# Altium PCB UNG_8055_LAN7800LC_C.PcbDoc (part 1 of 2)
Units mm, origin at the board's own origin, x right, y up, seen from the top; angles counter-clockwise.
Board outline 54.74 x 22.1 mm, 4 copper layers (Top Layer 1, Inner Layer 2, Internal Plane 3, Bottom Layer 4), stack 1.529 mm thick; 68 components, 53 nets, 222 pads, 271 vias.
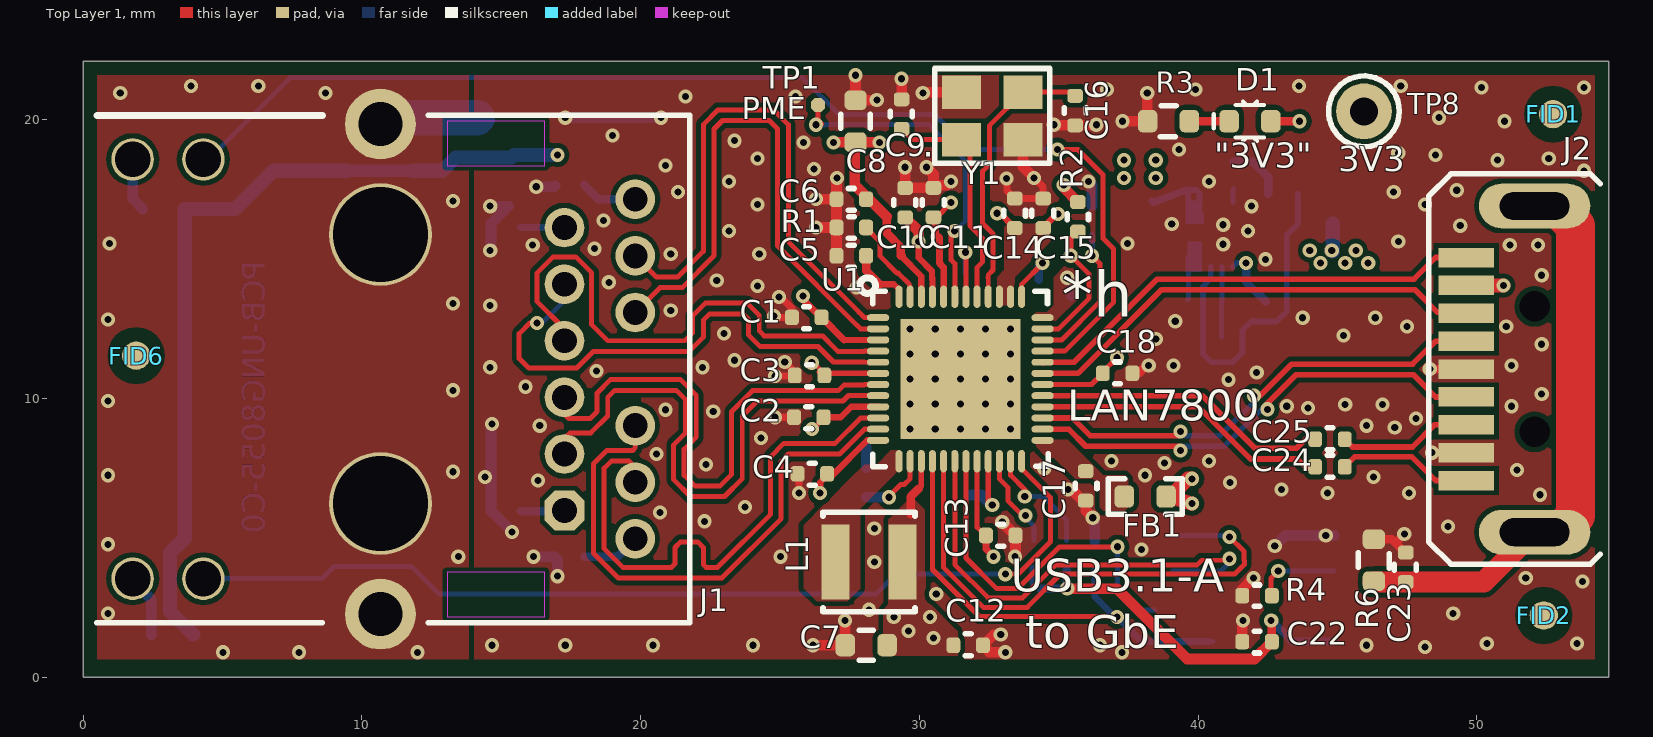
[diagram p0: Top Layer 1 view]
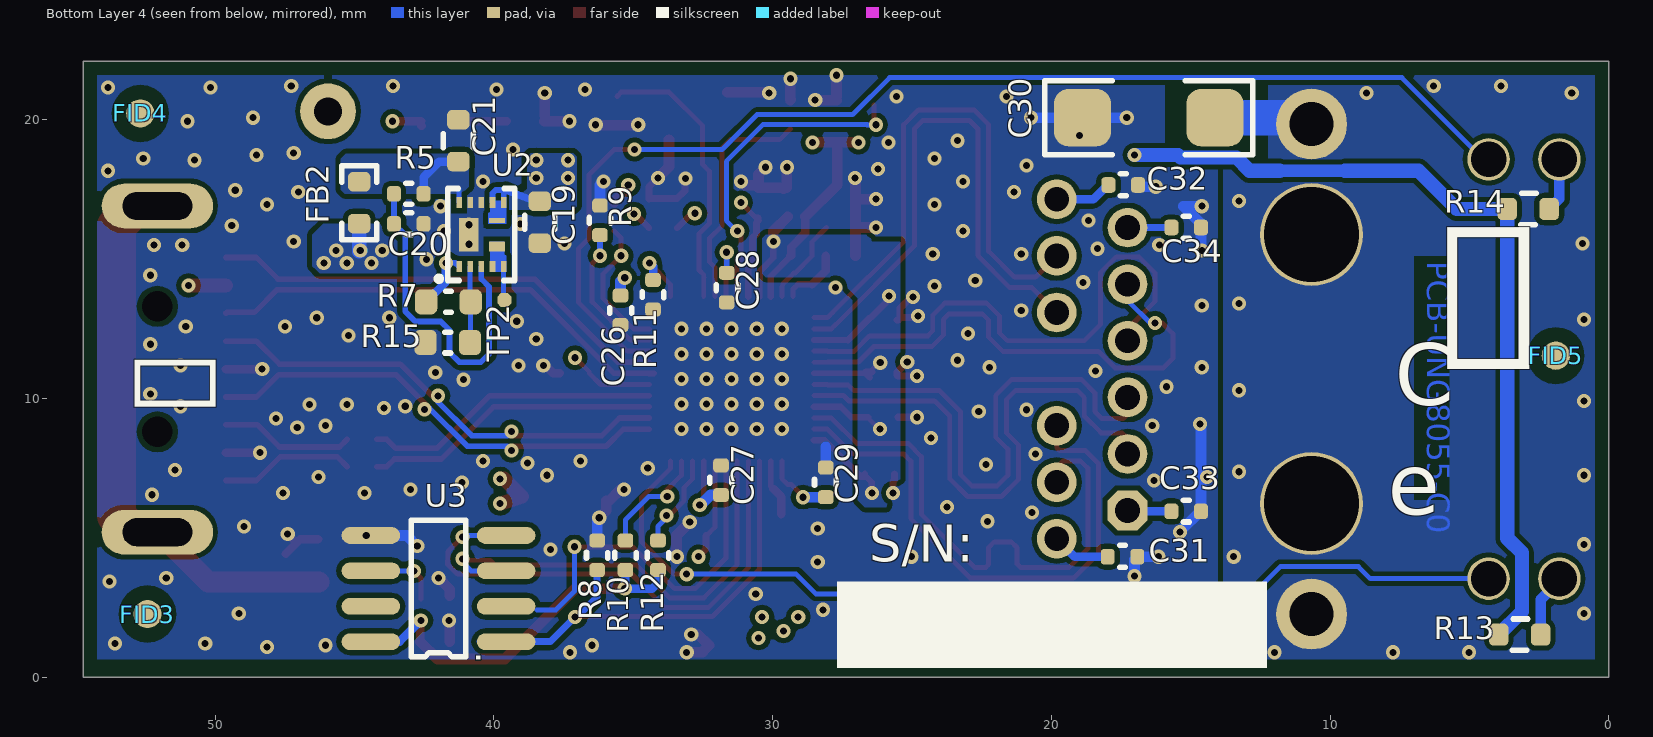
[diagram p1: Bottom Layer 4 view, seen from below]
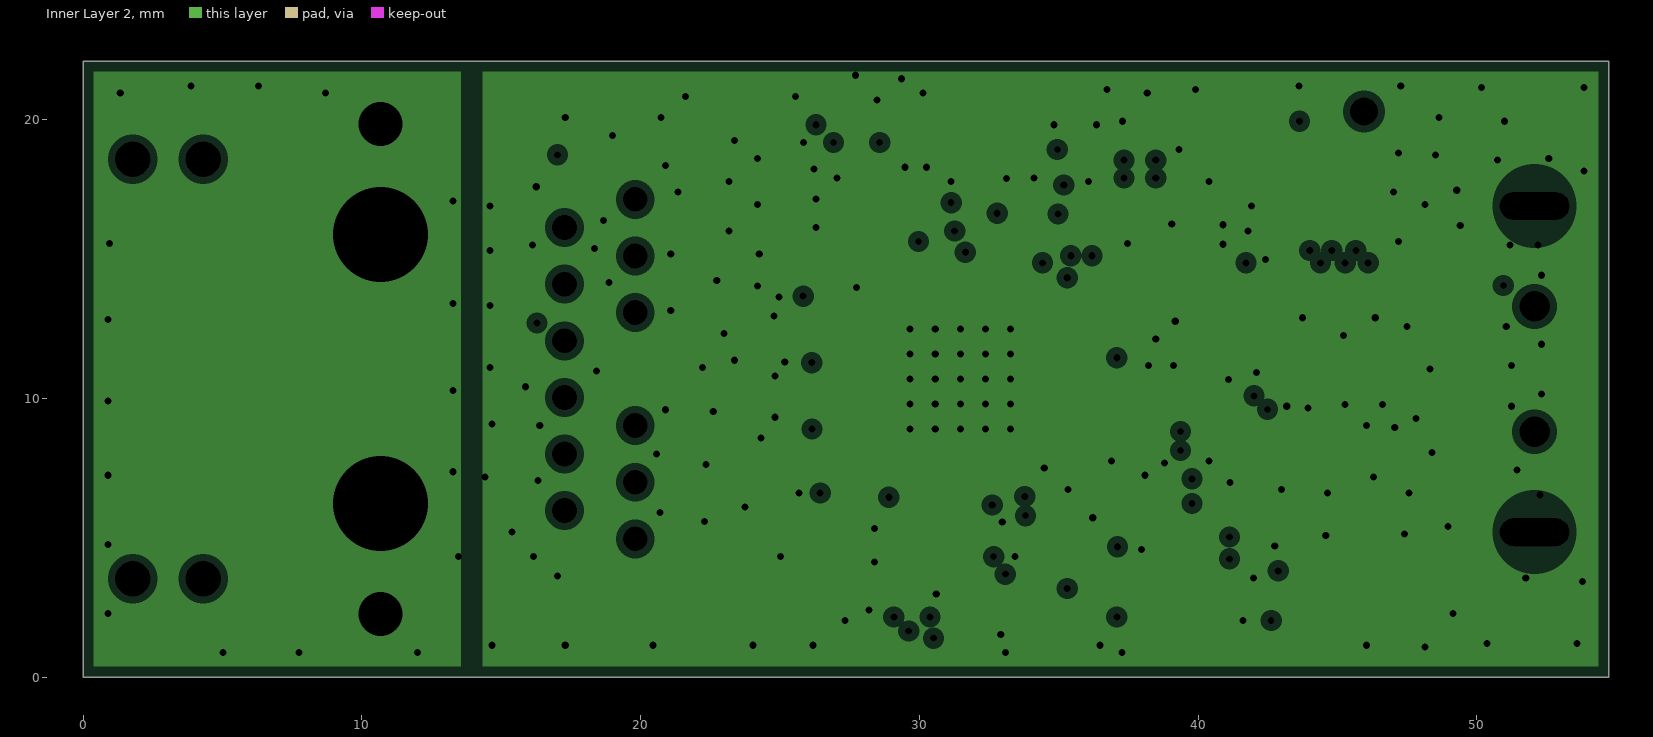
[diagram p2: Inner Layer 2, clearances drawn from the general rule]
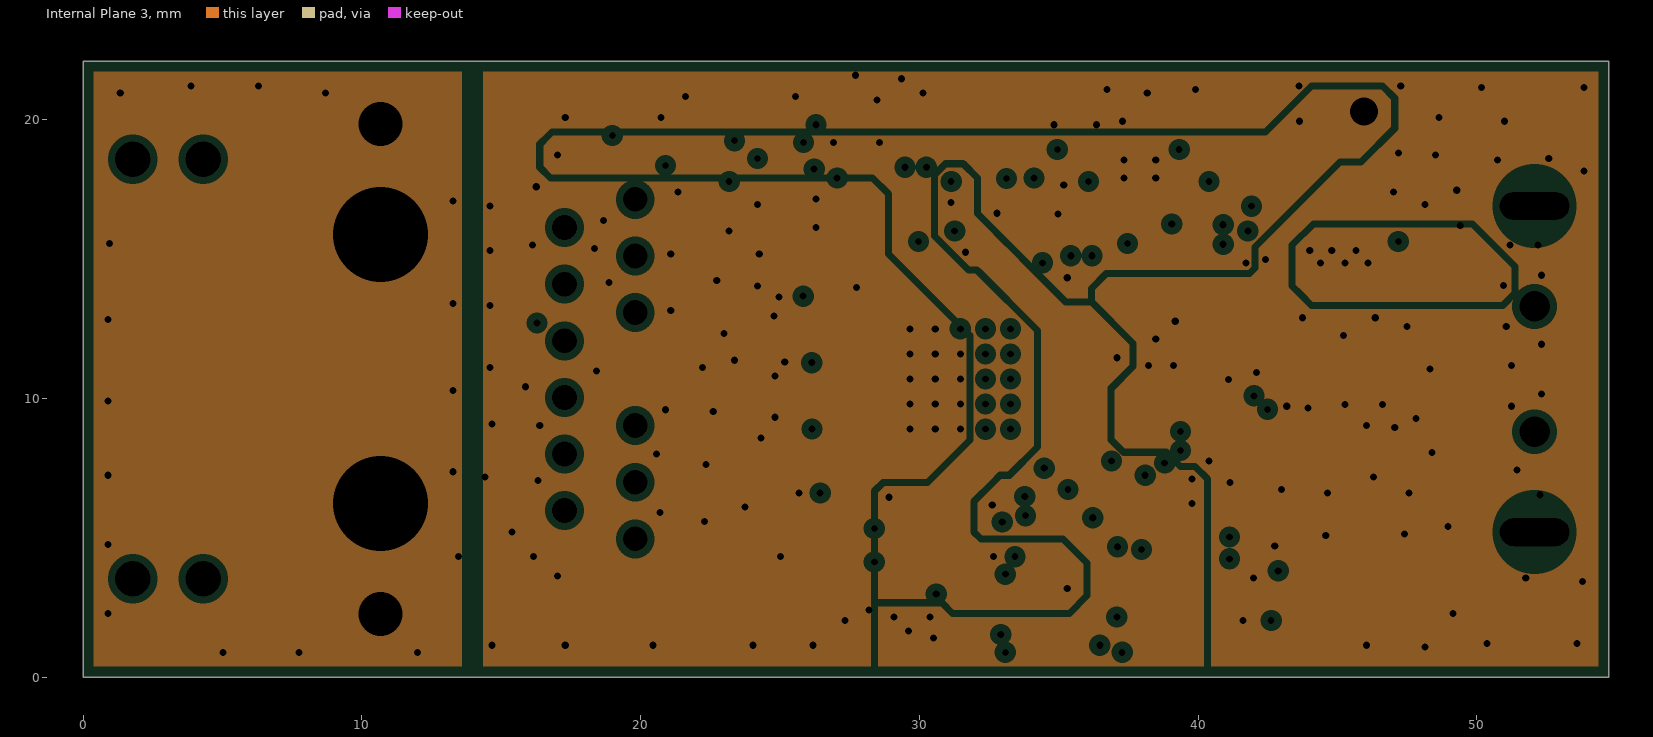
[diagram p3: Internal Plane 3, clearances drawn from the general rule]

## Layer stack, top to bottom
Top Solder: solder mask 0.0102, Solder Resist, Dk 3.5
Top Layer 1: signal copper 0.0533
Dielectric1: core 0.1092, 370HR(1ply 1080&1ply 106), Dk 4.04
Inner Layer 2: plane copper 0.0686
Dielectric 2: prepreg 1.0668, 370HR, Dk 4.04
Internal Plane 3: plane copper 0.0686
Dielectric 3: core 0.1092, 370HR(1ply 1080&1ply 106), Dk 4.04
Bottom Layer 4: signal copper 0.0533
Bottom Solder: solder mask 0.0102, Solder Resist, Dk 3.5

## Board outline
0,0 54.737,0 54.737,22.098 0,22.098

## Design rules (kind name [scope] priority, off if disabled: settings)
AssemblyTestPointUsage [All] p1 off:
AssemblyTestpoint [All] p1 off: testpointundercomponent=TRUE minsize=1.016 maxsize=2.54 preferedsize=1.524 minholesize=0 maxholesize=1.016 preferedholesize=0.813 testpointgrid=0.025 usegrid=TRUE gridtolerance=0 allowsidetop=TRUE allowsidebottom=TRUE
Clearance Dut_rules [WithinRoom('Dut_Room')] p1: gap=0.127 ignorepadtopadclearanceinfootprint=FALSE except(0: Arc-Hole Track-Hole SMDPad-Hole THPad-Hole Via-Hole Fill-Hole Poly-Hole Region-Hole Text-Hole)
Clearance USB_2_GND [InNetClass('Diff_90') vs InNet('GND')] p2: gap=0.178 ignorepadtopadclearanceinfootprint=FALSE except(0: Arc-Hole Track-Hole SMDPad-Hole THPad-Hole Via-Hole Fill-Hole Poly-Hole Region-Hole Text-Hole; 0.14: SMDPad-SMDPad; 0.152: Track-Track Track-SMDPad; 0.635: Track-Poly)
Clearance [All] p3: gap=0.178 ignorepadtopadclearanceinfootprint=FALSE except(0: Arc-Hole Track-Hole SMDPad-Hole THPad-Hole Via-Hole Fill-Hole Poly-Hole Region-Hole Text-Hole; 0.14: SMDPad-SMDPad; 0.152: Track-Track Track-SMDPad)
ComponentClearance [All] p1: gap=0 collisioncheckmode=3 verticalgap=0 showdistances=FALSE
DiffPairsRouting DiffPairsRouting_GBE [InNetClass('GBE')] p1: maxlimit=0.206 minlimit=0.201 mostfreqgap=0.203 toplayer_minwidth=0.175 toplayer_maxwidth=0.206 toplayer_prefwidth=0.178 bottomlayer_minwidth=0.175 bottomlayer_maxwidth=0.206 bottomlayer_prefwidth=0.178 maxuncoupledlength=12.7
DiffPairsRouting DiffPairsRouting_2P0 [InNetClass('Diff_90')] p2: maxlimit=0.203 minlimit=0.178 mostfreqgap=0.178 toplayer_minwidth=0.127 toplayer_maxwidth=0.208 toplayer_prefwidth=0.203 bottomlayer_minwidth=0.127 bottomlayer_maxwidth=0.208 bottomlayer_prefwidth=0.203 maxuncoupledlength=12.7
FabricationTestPointUsage TestPointUsage [All] p1 off: valid=0 allowmultiple=FALSE
FabricationTestpoint Testpoint [All] p1 off: side=3 testpointundercomponent=TRUE minsize=1.016 maxsize=2.54 preferedsize=1.524 minholesize=0 maxholesize=1.016 preferedholesize=0.813 testpointgrid=0.025 allowsidetop=TRUE allowsidebottom=TRUE usegrid=TRUE gridtolerance=0
HoleSize [All] p1: absolutevalues=TRUE maxlimit=5 minlimit=0.254 maxpercent=80.000 minpercent=20.000
MatchedLengths MatchedLengths2P0 [InNetClass('USB2.')] p1: tolerance=1.27 checknetsindiffpair=TRUE checkdiffpairvsdiffpair=FALSE checkxsignals=FALSE checkothers=FALSE
MatchedLengths MatchedLengths_GBE [InNetClass('GBE')] p2: tolerance=1.27 checknetsindiffpair=FALSE checkdiffpairvsdiffpair=TRUE checkxsignals=TRUE checkothers=TRUE
MatchedLengths MatchedLengths3P0 [InNetClass('USB3.')] p3: tolerance=0.127 checknetsindiffpair=TRUE checkdiffpairvsdiffpair=FALSE checkxsignals=FALSE checkothers=FALSE
MinimumSolderMaskSliver [All] p1: minsoldermaskwidth=0
NetsToIgnore [InNet('EARTH')] p1:
PlaneClearance [All] p1: clearance=0.254
PlaneConnect PlaneConnect_via [isVia] p1: planeconnectstyle=Direct reliefexpansion=0.5 reliefentries=4 reliefconductorwidth=0.3 reliefairgap=0.3
PlaneConnect [All] p2: planeconnectstyle=Relief reliefexpansion=0.381 reliefentries=4 reliefconductorwidth=0.457 reliefairgap=0.254
PolygonConnect PolygonConnect_top [All vs IsNamedPolygon('Top Layer-No Net')] p1: connectstyle=Direct reliefconductorwidth=0.254 reliefentries=4 polygonreliefangle="90 Angle" airgapwidth=0.254
PolygonConnect PolygonConnect_VIA [All vs iSVia] p2: connectstyle=Direct reliefconductorwidth=0.254 reliefentries=4 polygonreliefangle="90 Angle" airgapwidth=0.254
RoomDefinition UNG8055_EVB_LAN7800LC [InComponentClass('UNG8055_EVB_LAN7800LC')] p1: confinementstyle=ConfineIn formatcopy=TRUE lockcomponents=FALSE outline -88.255,-147.49 -37.455,-147.49 -37.455,-122.09 -88.255,-122.09
RoutingVias [All] p1: holewidth=0.254 width=0.508 viastyle="Through Hole" minholewidth=0.254 minwidth=0.495 maxholewidth=0.381 maxwidth=0.66
SilkToBoardRegionClearance SilkToBoardRegionClearance_1 [All] p1 off:
SilkToSilkClearance [All] p1: silktosilkclearance=0.127
SilkToSolderMaskClearance SilkscreenOverComponentPads [IsPad] p1: minsilkscreentomaskgap=0.127 clearancetoexposedcopper=TRUE
SolderMaskExpansion [All] p1: expansion=0.064
Width [All] p1: maxlimit=3.048 minlimit=0.152 preferedwidth=0.178 minimp=50.000000 maximp=50.000000 favimp=50.000000
17 further rules are at their usual default settings.

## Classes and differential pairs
net class GBE: TR0_N TR0_P TR1_N TR1_P TR2_N TR2_P TR3_N TR3_P
net class Power: 3V3_BOARD 5V_BOARD GND RJ45_CHASSIS VBUS VDD12 VDD12_SW_OUT VDD25
net class USB2.: USB2D_N USB2D_P
net class USB3.: USB3RX_N USB3RX_P USB3TX1_N USB3TX1_P USB3TX_N USB3TX_P
differential pair USB3TX1: +USB3TX1_P -USB3TX1_N
differential pair TR3: +TR3_P -TR3_N
differential pair TR2: +TR2_P -TR2_N
differential pair TR1: +TR1_P -TR1_N
differential pair TR0: +TR0_P -TR0_N
differential pair USB3RX: +USB3RX_P -USB3RX_N
differential pair USB2D: +USB2D_P -USB2D_N
differential pair USB3TX: +USB3TX_P -USB3TX_N

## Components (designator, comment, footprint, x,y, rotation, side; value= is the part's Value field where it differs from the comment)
C1 "Capacitor NP" CAP_C_0402 25.959,12.903 r0 top value=0.1uF
C2 "Capacitor NP" CAP_C_0402 26.035,9.322 r0 top value=0.1uF
C3 "Capacitor NP" CAP_C_0402 26.06,10.82 r0 top value=0.1uF
C4 "Capacitor NP" CAP_C_0402 26.162,7.29 r0 top value=0.1uF
C5 "Capacitor NP" CAP_C_0402 27.559,15.113 r0 top value=1uF
C6 "Capacitor NP" CAP_C_0402 27.559,17.145 r0 top value=1uF
C7 "Capacitor NP" CAP_C_0603 28.092,1.143 r0 top value=22uF
C8 "Capacitor NP" CAP_C_0603 27.711,19.939 r270 top value=10uF
C9 "Capacitor NP" CAP_C_0402 29.362,20.193 r270 top value=16pF
C10 "Capacitor NP" CAP_C_0402 29.489,17.018 r270 top value=1uF
C11 "Capacitor NP" CAP_C_0402 30.505,17.018 r270 top value=0.1uF
C12 "Capacitor NP" CAP_C_0402 31.75,1.143 r180 top value=0.1uF
C13 "Capacitor NP" CAP_C_0402 32.918,5.08 r180 top value=0.1uF
C14 "Capacitor NP" CAP_C_0402 33.426,16.637 r270 top value=0.1uF
C15 "Capacitor NP" CAP_C_0402 34.442,16.637 r270 top value=0.1uF
C16 "Capacitor NP" CAP_C_0402 35.585,20.32 r90 top value=16pF
C17 "Capacitor NP" CAP_C_0402 35.966,6.858 r90 top value=1uF
C18 "Capacitor NP" CAP_C_0402 37.109,10.897 r180 top value=0.1uF
C19 "Capacitor NP" CAP_C_0603 38.354,16.319 r90 bottom value=10uF
C20 "Capacitor NP" CAP_C_0402 43.053,16.256 r0 bottom value=0.1uF
C21 "Capacitor NP" CAP_C_0603 41.275,19.241 r270 bottom value=10uF
C22 "Capacitor NP" CAP_C_0402 42.113,1.27 r0 top value=0.1uF
C23 "Capacitor NP" CAP_C_0402 47.447,3.937 r270 top value=0.1uF
C24 "Capacitor NP" CAP_C_0402 44.729,7.544 r180 top value=0.1uF
C25 "Capacitor NP" CAP_C_0402 44.729,8.531 r180 top value=0.1uF
C26 "Capacitor NP" CAP_C_0402 35.458,13.157 r90 bottom value=0.1uF
C27 "Capacitor NP" CAP_C_0402 31.852,7.061 r270 bottom value=0.1uF
C28 "Capacitor NP" CAP_C_0402 31.648,13.97 r90 bottom value=0.1uF
C29 "Capacitor NP" CAP_C_0402 28.092,6.985 r270 bottom value=0.1uF
C30 "Capacitor NP" Cap_C_1808 16.51,20.066 r180 bottom value=1000pF
C31 "Capacitor NP" CAP_C_0402 17.45,4.318 r0 bottom value=0.1uF
C32 "Capacitor NP" CAP_C_0402 17.424,17.653 r0 bottom value=0.1uF
C33 "Capacitor NP" CAP_C_0402 15.164,5.944 r0 bottom value=0.1uF
C34 "Capacitor NP" CAP_C_0402 15.164,16.129 r0 bottom value=0.1uF
D1 "LED_green" LED_0603_GREEN 41.859,19.939 r180 top value=GREEN
FB1 "Ferrite Bead" IND_C_0603 38.1,6.477 r0 top value=120R
FB2 "Ferrite Bead" Ind_C_0603 44.831,17.018 r90 bottom value=120R
FID1 "FIDUCIAL" FIDUCIAL 52.73,20.193 r90 top
FID2 "FIDUCIAL" FIDUCIAL 52.4,2.21 r90 top
FID3 "FIDUCIAL" FIDUCIAL 52.426,2.261 r90 bottom
FID4 "FIDUCIAL" FIDUCIAL 52.68,20.218 r90 bottom
FID5 "FIDUCIAL" FIDUCIAL 1.905,11.532 r90 bottom
FID6 "FIDUCIAL" FIDUCIAL 1.905,11.532 r90 top
J1 "CON RJ-45 RJMG2012211A0FR" CON_JACK_RJ45_1PORT_LED_RJMG2012211A0FR 10.668,11.049 r270 top value="MODULAR RJ45"
J2 "CON USB3.0 A-B" CON_USB3.0-A_PLUG_SMD_RA_WE_692112030100 52.07,11.049 r90 top locked value="USB3.0 STD-A MALE"
L1 "Inductor" IND_WE_74404032033_L3W3H1.5 28.194,4.127 r0 top value=3.3uH
R1 "Resistor" RES_C_0402 27.559,16.129 r180 top value=2k
R2 "Resistor" RES_C_0402 35.687,16.51 r90 top value=10k
R3 "Resistor" RES_C_0603#1 38.938,19.939 r0 top value=1k
R4 "Resistor" RES_C_0402 42.113,2.921 r0 top value=10k
R5 "Resistor" RES_C_0402 43.053,17.335 r180 bottom value=10k
R6 "Resistor" RES_C_0603#1 46.304,4.191 r90 top value=330R
R7 "Resistor" RES_C_0603#2 41.63,13.462 r0 bottom value=866k
R8 "Resistor" RES_C_0402 36.297,4.369 r270 bottom value=10k
R9 "Resistor" RES_C_0402 36.195,16.383 r270 bottom value=10k
R10 "Resistor" RES_C_0402 35.281,4.369 r270 bottom value=10k
R11 "Resistor" RES_C_0402 34.29,13.716 r90 bottom value=12k
R12 "Resistor" RES_C_0402 34.112,4.369 r270 bottom value=10k
R13 "Resistor" RES_C_0603#1 3.2,1.524 r0 bottom value=1k
R14 "Resistor" RES_C_0603#1 2.896,16.789 r0 bottom value=1k
R15 "Resistor" RES_C_0603#2 41.656,12.002 r180 bottom value=200k
TP1 "Jumper" TP_PAD_SMT_20OCTAGONAL 26.365,20.523 r90 top
TP2 "Jumper" TP_PAD_SMT_20OCTAGONAL 39.624,13.525 r90 bottom
TP8 "Test Point" CON_TP_TH_V_ORN_KEC_5003 45.949,20.295 r90 top value=Orange
U1 "LAN7800 QFN-48 TEST" QFN-48_6X6 31.471,10.693 r0 top value=LAN7800/VSX
U2 "MIC33030-AYHJ MLF-10" MLF-10_2.5x2.0mm 40.449,15.875 r90 bottom value=MIC33030-AYHJ
U3 "93XX66A_B_C PDIP-8_SOIC-8_TSSOP-8_MSOP-8" SOIC-8_150MIL 41.986,3.175 r0 bottom value=93AA66C
Y1 "Crystal 4 Pins" CRYSTAL_ABM8G 32.614,20.13 r0 top value=25Mhz

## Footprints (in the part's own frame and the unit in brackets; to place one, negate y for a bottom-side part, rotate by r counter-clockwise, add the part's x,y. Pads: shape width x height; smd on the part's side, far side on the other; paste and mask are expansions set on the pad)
CAP_C_0402 [mm] "Chip Capacitor 2-Leads, Body 1.6x0.8mm, IPC Medium Density"
  rrect50% 0.5x0.56 smd: 1(-0.53,0) 2(0.53,0)
  silkscreen extent -0.1,-0.41 0.1,0.38, body extent -0.5,-0.25 0.5,0.25, height 0.49
CAP_C_0603 [mm] "Chip Capacitor 2-Leads, Body 1.6x0.8mm, IPC Medium Density"
  rrect50% 0.7x0.8 smd: 1(-0.75,0) 2(0.75,0)
  silkscreen extent -0.25,-0.53 0.25,0.53, body extent -0.8,-0.4 0.8,0.4, height 0.79
Cap_C_1808 [mm] "Chip Capacitor 2-Leads, Body 4.5 x 2.0mm, IPC Medium Density"
  rrect50% 2.05x2.05 smd: 1(-2.375,0) 2(2.375,0)
  silkscreen extent -3.72,-1.33 3.72,1.33, body extent -2.25,-1.03 2.25,1, height 1.25
CON_JACK_RJ45_1PORT_LED_RJMG2012211A0FR [mm] "CONN MAGJACK 1PORT 1000 BASE-T AMPHENOL RJMG2012211A0FR"
  round 2.54 hole 1.57: 0(-8.79,0) 0(8.79,0)
  round 3.683 hole 3.4: 0(-4.825,0) 0(4.825,0)
  oct 1.422x1.422 hole 0.89: 1(5.075,6.6)
  round 1.422 hole 0.89: 2(3.045,6.6) 3(1.015,6.6) 4(-1.015,6.6) 5(-3.045,6.6) 6(-5.075,6.6) 7(6.09,9.14) 8(4.06,9.14) 9(2.03,9.14) 10(-2.03,9.14) 11(-4.06,9.14) 12(-6.09,9.14)
  round 1.524 hole 1.27: 13(7.52,-6.35) 14(7.52,-8.89) 15(-7.52,-6.35) 16(-7.52,-8.89)
  Top Layer 1 keep-out region: -8.89,2.39 -7.29,2.39 -7.29,5.89 -8.89,5.89
  Top Layer 1 keep-out region: 7.29,2.39 8.89,2.39 8.89,5.89 7.29,5.89
  silkscreen extent -9.1,-10.18 9.1,11.1, body extent -9.96,-13.27 9.96,10.87, height 11.96
CON_TP_TH_V_ORN_KEC_5003 [mm] "TEST POINT PC MULTI PURPOSE MINI ORN"
  round 2 hole 1: 1(0,0)
  silkscreen extent -1.27,-1.27 1.27,1.27, body extent -1.27,-1.27 1.27,1.27, height 4.89
CON_USB3.0-A_PLUG_SMD_RA_WE_692112030100 [mm] "CONN USB 3.0 A PLUG SMD R/A EDGE L=18.8mm, W=12mm, H=4.5mm"
  oval 1.6x4 hole 1 slot 2.5 at 90 deg: 0(-5.85,0) 0(5.85,0)
  rect 0.7x2 smd: 1(3,2.45) 2(1,2.45) 3(-1,2.45) 4(-3,2.45) 5(-4,2.45) 6(-2,2.45) 7(0,2.45) 8(2,2.45) 9(4,2.45)
  round 0 hole 1.1 unplated paste-1 mask+0.65: MH(-2.25,0) MH(2.25,0)
  silkscreen extent -7,-2.35 7,3.8, body extent -6,-17.8 6,2.95, height 1.86
CRYSTAL_ABM8G [mil]
  rect 55x47 smd: 1(-43.5,-33.5) 2(43.5,-33.5) 3(43.5,33.5) 4(-43.5,33.5)
  silkscreen extent -81,-67 81,67, body extent -63,-49 63,49, height 40
FIDUCIAL [mil]
  round 40 smd mask+20: 1(0,0)
  Top Layer 1 pour cut-out: 40.35,0 38.97,10.44 34.94,20.17 28.53,28.53 20.17,34.94 10.44,38.97 0,40.35 0,40.35 -10.44,38.97 -20.17,34.94 -28.53,28.53 -34.94,20.17 -38.97,10.44 -40.35,0 -40.35,0 -38.97,-10.44 -34.94,-20.17 -28.53,-28.53 -20.17,-34.94 -10.44,-38.97 0,-40.35 0,-40.35 10.44,-38.97 20.17,-34.94 28.53,-28.53 34.94,-20.17 38.97,-10.44 40.35,0
  body extent -40,-40 40,40, height 0
IND_C_0603 [mm] "Chip Inductor 2-Leads, Body 1.6x0.8mm, IPC Medium Density"
  rrect50% 0.7x0.8 smd: 1(-0.75,0) 2(0.75,0)
  silkscreen extent -1.33,-0.63 1.33,0.63, body extent -1.33,-0.63 1.32,0.63, height 0.81
Ind_C_0603 [mm] "Chip Inductor 2-Leads, Body 1.6x0.8mm, IPC Medium Density"
  rrect50% 0.7x0.8 smd: 1(-0.75,0) 2(0.75,0)
  silkscreen extent -1.33,-0.63 1.33,0.63, body extent -1.33,-0.63 1.32,0.63, height 0.81
IND_WE_74404032033_L3W3H1.5 [mm]
  rect 1x2.7 smd: 1(-1.2,0) 2(1.2,0)
  silkscreen extent -1.65,-1.78 1.65,1.78, body extent -1.48,-1.5 1.52,1.5, height 1.5
LED_0603_GREEN [mm] "LED chip 0603 - GREEN"
  rrect50% 0.7x0.8 smd: 1(-0.75,0) 2(0.75,0)
  silkscreen extent -0.51,-0.71 1.3,0.71, body extent -1.33,-0.63 1.32,0.63, height 0.6
MLF-10_2.5x2.0mm [mm] "MLF 10-Leads, Body 2.55x2.05mm (max), Pitch 0.40mm, IPC Medium Density"
  rrect0% 0.4x0.2 smd mask+0.05: 1(-1.15,0.8) 2(-1.15,0.4) 3(-1.15,0) 4(-1.15,-0.4) 5(-1.15,-0.8) 6(1.15,-0.8) 7(1.15,-0.4) 8(1.15,0) 9(1.15,0.4) 10(1.15,0.8)
  rect 0.36x0.58 smd mask+0.05: 4(-0.43,-0.56)
  rect 0.18x0.58 smd mask+0.05: 7(0.51,-0.56)
  rect 1.2x0.7 smd mask+0.05: EP(0,0.45)
  silkscreen extent -1.65,-1.2 1.65,1.52, body extent -1.28,-1.02 1.28,1.03, height 1.15
QFN-48_6X6 [mm] "QFN, 48-Leads, Body 6x6mm, Pitch 0.4mm, Thermal Pad 4.3mmsq"
  oval 0.8x0.25 smd: 1(-2.95,2.2) 2(-2.95,1.8) 3(-2.95,1.4) 4(-2.95,1) 5(-2.95,0.6) 6(-2.95,0.2) 7(-2.95,-0.2) 8(-2.95,-0.6) 9(-2.95,-1) 10(-2.95,-1.4) 11(-2.95,-1.8) 12(-2.95,-2.2) 25(2.95,-2.2) 26(2.95,-1.8) 27(2.95,-1.4) 28(2.95,-1) 29(2.95,-0.6) 30(2.95,-0.2) 31(2.95,0.2) 32(2.95,0.6) 33(2.95,1) 34(2.95,1.4) 35(2.95,1.8) 36(2.95,2.2)
  oval 0.25x0.8 smd: 13(-2.2,-2.95) 14(-1.8,-2.95) 15(-1.4,-2.95) 16(-1,-2.95) 17(-0.6,-2.95) 18(-0.2,-2.95) 19(0.2,-2.95) 20(0.6,-2.95) 21(1,-2.95) 22(1.4,-2.95) 23(1.8,-2.95) 24(2.2,-2.95) 37(2.2,2.95) 38(1.8,2.95) 39(1.4,2.95) 40(1,2.95) 41(0.6,2.95) 42(0.2,2.95) 43(-0.2,2.95) 44(-0.6,2.95) 45(-1,2.95) 46(-1.4,2.95) 47(-1.8,2.95) 48(-2.2,2.95)
  rect 4.3x4.3 / inner round 0.508 / far side round 0.508 hole 0.254 mask+0.051: 49(0,0)
  silkscreen extent -3.6,-3.15 3.15,3.63, body extent -3.02,-3.02 3.02,3.02, height 0.91
RES_C_0402 [mm] "Chip Resistor, 2-Leads, Body 1.0x0.5mm, IPC Medium Density"
  rrect50% 0.5x0.56 smd: 1(-0.53,0) 2(0.53,0)
  silkscreen extent -0.1,-0.38 0.1,0.38, body extent -0.5,-0.25 0.5,0.25, height 0.34
RES_C_0603#1 [mm] "Chip Resistor, 2-Leads, Body 1.6x0.8mm, IPC Medium Density"
  rrect50% 0.7x0.8 smd: 1(-0.75,0) 2(0.75,0)
  silkscreen extent -0.29,-0.56 0.27,0.56, body extent -0.8,-0.4 0.8,0.4, height 0.45
RES_C_0603#2 [mm] "Chip Resistor, 2-Leads, Body 1.6x0.8mm, IPC Medium Density"
  rrect50% 0.8x0.9 smd: 1(-0.8,0) 2(0.8,0)
  silkscreen extent -0.1,-0.38 0.1,0.38, body extent -0.8,-0.4 0.8,0.4, height 0.3
SOIC-8_150MIL [mm] "SOIC-8 Narrow"
  oval 2.1x0.6 smd: 1(-2.425,1.905) 2(-2.425,0.635) 3(-2.425,-0.635) 4(-2.425,-1.905) 5(2.425,-1.905) 6(2.425,-0.635) 7(2.425,0.635) 8(2.425,1.905)
  silkscreen extent -0.97,-2.45 0.98,2.45, body extent -2.96,-2.5 3.06,2.5, height 1.75
TP_PAD_SMT_20OCTAGONAL [mil] "TEST POINT, SMT PAD20OCTAGONAL"
  oct 20x20 smd: 1(0,0)

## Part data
C1 C2 C3 C4 C11 C12 C13 C14 C15 C18 C20 C22 C23 C24 C25 C26 C27 C28 C29 C31 C32 C33 C34: library part CAP1337, "Capacitor", Manufacturer 1="TDK Corporation", Manufacturer Part Number 1=CGA2B3X7R1V104K050BB, Operating Temperature="-55C to 125C", Package=0402, Supplier Part Number 1=445-6901-1-ND, Temperature Coeffcient=X7R, Tolerance=10%, Voltage=35V
C5 C6 C10 C17: library part CAP1065, "Capacitor", Manufacturer 1="TDK Corporation", Manufacturer Part Number 1=C1005X5R1C105K, Operating Temperature="-55C to +85C", Package=0402, Supplier Part Number 1=445-4978-2-ND, Temperature Coeffcient=X5R, Tolerance=10%, Voltage=16V
C7: library part CAP1366, "Capacitor", Manufacturer 1="Samsung Electro-Mechanics America, Inc", Manufacturer Part Number 1=CL10A226MQ8NRNC, Operating Temperature="-55C to +85C", Package=0603, Supplier Part Number 1=1276-1193-1-ND, Temperature Coeffcient=X5R, Voltage=6.3V
C8 C19 C21: library part CAP1461, "Capacitor", Manufacturer 1="Murata Electronics North America", Manufacturer Part Number 1=GRM188R61E106MA73D, Operating Temperature="-55C to 85C", Package=0603, Supplier Part Number 1=490-7202-1-ND, Temperature Coeffcient=X5R, Tolerance=±20%, Voltage=25V
C9 C16: library part CAP1767, "Capacitor", Manufacturer 1="Murata Electronics North America", Manufacturer Part Number 1=GRM1555C1H160JA01D, Operating Temperature="-55°C ~ 125°C", Package=0402, Supplier Part Number 1=490-5926-1-ND, Temperature Coeffcient=NPO, Tolerance=5%, Voltage=50V
C30: library part CAP1775, "Capacitor", Manufacturer 1="Murata Electronics North America", Manufacturer Part Number 1=GR442QR73D102KW01L, Operating Temperature="-55°C ~ 125°C", Supplier Part Number 1=490-8145-1-ND, Temperature Coeffcient=X7R, Tolerance=10%, Voltage=2KV
D1: library part DIODE1155, "LED", Forward Current=30mA, Manufacturer 1="Lite-On Inc", Manufacturer 2=Ledtech, Manufacturer Part Number 1=LTST-C191KGKT, Manufacturer Part Number 2=LT8A23-54-SB96-T5, Operating Temperature="-55C to +85C", Power=75mW, Reverse Voltage=5V, Supplier Part Number 1=160-1446-1-ND
FB1 FB2: library part FB1003, Manufacturer 1="TDK Corporation", Manufacturer Part Number 1=MMZ1608B121CTAH0, Supplier Part Number 1=445-2164-1-ND
J1: library part CON1827, Manufacturer 1="Amphenol Commercial Products", Manufacturer Part Number 1=RJMG2012211A0FR, Supplier Part Number 1=RJMG2012211A0FR-ND
J2: library part CON1255, "Connector USB", Current=1.8A, Manufacturer 1="Wurth Electronics Inc", Manufacturer Part Number 1=692112030100, Supplier Part Number 1=732-3157-ND, Voltage=30V
L1: library part IND1557, Manufacturer 1="Wurth Electronics Inc.", Manufacturer Part Number 1=74404032033, Operating Temperature="-40°C ~ 125°C", Package=3015, Saturation Current=1.5A, Supplier Part Number 1=732-5494-1-ND, Test Frequency=100kHz
R1: library part RES1437, Manufacturer 1="Panasonic Electronic Components", Manufacturer Part Number 1=ERJ-2RKF2001X, Operating Temperature="-55°C ~ 155°C", Package=0402, Power=1/10W, Supplier Part Number 1=P2.00KLCT-ND, Temperature Coeffcient=±100ppm/°C, Tolerance=1%
R2 R4 R5 R8 R9 R10 R12: library part RSMT1019, Manufacturer 1=Panasonic, Manufacturer Part Number 1=ERJ-2RKF1002X, Operating Temperature="-55C to +155C", Package=0402, Power=1/10W, Supplier Part Number 1=P10.0KLCT-ND, Temperature Coeffcient=100ppm/C, Tolerance=1%, Voltage=50V
R3 R13 R14: library part RSMT0047, Manufacturer 1=Panasonic, Manufacturer 2="KOA Speer", Manufacturer 4=ROHM, Manufacturer 6="Stackpole Electronics Inc", Manufacturer 7=Yageo, Manufacturer Part Number 1=ERJ-3GEYJ102V, Manufacturer Part Number 2=RK73B1JTTD102J, Manufacturer Part Number 3=ERJ-3GSYJ102V, Manufacturer Part Number 4=MCR03EZHJ1K, Manufacturer Part Number 5=MCR03FZHJ1001, Manufacturer Part Number 6="RMCF 1/16 1K 5% R", Manufacturer Part Number 7=RC0603JR-071KL, Operating Temperature="-55C to +155C", Package=0603, Power=1/10W, Supplier Part Number 1=P1.0KGCT-ND, Temperature Coeffcient=200ppm/C, Tolerance=5%, Voltage=75V
R6: library part RES1346, Manufacturer 1="Panasonic Electronic Components", Manufacturer Part Number 1=ERA-V33J331V, Operating Temperature="-40C to +125C", Package=0603, Power=1/16W, Supplier Part Number 1=P330CHTR-ND, Temperature Coeffcient=3300ppm/C, Tolerance=5%
R7: library part RSMT1204, Manufacturer 1=Yageo, Manufacturer Part Number 1=RC0603FR-07866KL, Operating Temperature="-55C to +155C", Package=0603, Power=1/10W, Supplier Part Number 1=311-866KHRCT-ND, Temperature Coeffcient=100ppm/C, Tolerance=1%, Voltage=75V
R11: library part RES1021, Manufacturer 1="Rohm Semiconductor", Manufacturer Part Number 1=MCR01MZPF1202, Operating Temperature="-55C to +155C", Package=0402, Power=1/16W, Supplier Part Number 1=RHM12.0KLCT-ND, Temperature Coeffcient=400ppm/C, Tolerance=1%, Voltage=50V
R15: library part RES1140, Manufacturer 1=Vishay, Manufacturer Part Number 1=CRCW0603200KFKEA, Operating Temperature="-55C to +155C", Package=0603, Power=1/10W, Supplier Part Number 1=541-200KHCT-ND, Temperature Coeffcient=100ppm/C, Tolerance=1%, Voltage=75V
TP1 TP2: library part "TEST PAD SMT 20 OCTAGON", "TEST PAD SMT 20 OCTAGON", Manufacturer=none
TP8: library part CON1282, Manufacturer 1="Keystone Electronics", Manufacturer Part Number 1=5003, Supplier Part Number 1=5003K-ND
U1: library part MIC7903, Manufacturer 1="Microchip Technology Inc", Manufacturer Part Number 1=LAN7800/VSX
U2: library part MIC7400, Manufacturer 1=Microchip, Manufacturer Part Number 1=MIC33030-AYHJ-TR, Supplier Part Number 1=576-3720-1-ND
U3: library part MIC7670, Manufacturer 1="Microchip Technology", Manufacturer Part Number 1=93AA66C-I/SN, MaxClockFreq="3 MHz", OpVoltMax=5.5, OpVoltMin=1.8, PackageType=SOIC, PackageWidth=3.90mm(.150in), Supplier Part Number 1=93AA66C-I/SN-ND, TempRange="-40C to +85C"
Y1: library part OSC1196, Load Capacitance=10pF, Manufacturer 1="Abracon LLC", Manufacturer Part Number 1=ABM8G-25.000MHZ-B4Y-T, Operating Temperature="-20°C ~ 70°C", Package=ABM8G, Supplier Part Number 1=535-10297-1-ND, Tolerance=±30ppm

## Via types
v1: diameter 0.508, hole 0.254, Top Layer 1 to Bottom Layer 4, tented both sides, 245 vias
v2: diameter 0.508, hole 0.254, Top Layer 1 to Bottom Layer 4, 26 vias

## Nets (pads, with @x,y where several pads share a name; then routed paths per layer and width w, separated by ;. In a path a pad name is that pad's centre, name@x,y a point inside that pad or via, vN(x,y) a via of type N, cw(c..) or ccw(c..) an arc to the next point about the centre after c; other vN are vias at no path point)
3V3_BOARD: C6.2 C8.2 C13.2 C14.2 C15.2 C19.2 C22.2 C26.2 C29.2 D1.1 R2.2 R7.2 R10.2 R12.2 R13.2 R14.2 TP8.1 U1.14 U1.20 U1.36 U1.38 U1.39 U1.46 U2.1 U2.6 U2.7 U3.8 | length 67.9
  Top Layer 1 w0.178: v1@28.931,6.502 29.337,6.909 29.464,6.909 29.671,7.115 U1.14@29.671,7.743 ; U1.20@32.071,7.743 32.071,5.369 C13.2@32.36,5.08
  Top Layer 1 w0.229: 29.362,15.113 29.362,15.088 30.071,14.379 U1.46@30.071,13.643 ; v1(32.791,16.637) v1@32.791,16.742 ; v1@32.813,16.764 v1@32.791,16.742 ; C14.2@33.426,16.107 v1@32.791,16.742 ; C15.2@34.442,16.107 34.442,16.129 34.936,16.622 34.95,16.608 34.954,16.612 v1(34.976,16.612)
  Top Layer 1 w0.254: C13.2@32.388,5.08 32.388,4.594 v1(32.664,4.318)
  Top Layer 1 w0.305: 28.829,16.51 28.829,15.924 29.337,15.416 29.337,15.113 29.362,15.113 ; D1.1@42.584,19.769 D1.1@42.609,19.769 ; D1.1@42.609,19.939 v1(43.637,19.939) ; C22.2@42.643,1.27 v1@42.643,2.01
  Top Layer 1 w0.381: v1(26.924,19.177) 26.936,19.189 27.686,19.189 27.686,17.653 28.829,16.51 ; C8.2@27.711,19.189 28.557,19.189 28.569,19.177 v1(28.575,19.177) ; v1(35.179,17.653) 35.179,17.548 R2.2@35.687,17.04 ; v1(35.306,3.175) 37.084,3.175 39.612,0.647 42.02,0.647 C22.2@42.643,1.27
  Bottom Layer 4 w0.203: U2.6@39.65,17.025 39.65,17.406 39.586,17.47 39.934,17.47 40.05,17.354 U2.7@40.05,17.025 ; U2.1@41.25,14.725 41.384,14.859 v1(41.719,14.859)
  Bottom Layer 4 w0.254: C19.2@38.354,17.07 38.399,17.025 39.586,17.47
  Bottom Layer 4 w0.305: R12.2@34.112,3.886 R12.2@34.112,3.839 34.112,3.378 34.315,3.175 v1(35.306,3.175) ; v1@35.281,3.251 R10.2@35.281,3.839 ; v1(41.719,14.859) 41.719,14.173 R7.2@42.431,13.462 ; v1(42.621,2.032) 43.383,1.27 U3.8@44.411,1.27 U3.8@44.882,1.27
  Bottom Layer 4 w0.381: C29.2@28.092,6.455 28.876,6.455 v1@28.905,6.426 ; v1@35.306,14.351 35.458,14.199 C26.2@35.458,13.687
  Bottom Layer 4 w0.457: 9.463,18.163 11.809,18.163
  Bottom Layer 4 w0.508: R13.2@3.95,1.524 3.124,2.35 3.124,4.458 3.646,4.979 R14.2@3.646,16.789 5.461,16.789 6.834,18.163 9.463,18.163 ; 11.809,18.163 12.892,18.163 13.364,18.635 15.367,18.635 15.465,18.732 v1(17.018,18.732)
  other v1: 28.905,6.452 35.306,14.326 37.338,17.907 38.481,17.907 37.338,18.542 38.481,18.542
5V_BOARD: C21.2 FB2.2 R5.2 U2.10 | length 2.6
  Bottom Layer 4 w0.178: U2.10@41.25,17.025 41.25,17.5 41.275,17.525
  Bottom Layer 4 w0.305: C21.2@41.275,18.49 41.962,18.49 42.523,17.929 R5.2@42.523,17.335
EARTH_GND: C23.2 J2.0 R6.1 | length 20.4
  Top Layer 1 w0.762: R6.1@46.279,3.407 C23.2@47.447,3.407 50.245,3.407 J2.0@52.019,5.182
  Top Layer 1 w1.397: J2.0@52.07,5.199 52.951,5.199 53.543,5.791 53.543,16.18 52.756,16.967 J2.0@52.095,16.967
EECLK: U1.19 U3.2 | length 13.2
  Top Layer 1 w0.178: U1.19@31.671,7.743 31.671,4.27 32.771,3.17 33.528,3.17 ; 33.528,3.175 35.027,4.674 v1(37.109,4.674)
  Bottom Layer 4 w0.178: v1(37.109,4.674) 37.109,3.073 37.77,2.413 38.456,2.413
EECS: R8.2 U1.16 U3.1 | length 17
  Top Layer 1 w0.178: U1.16@30.471,7.743 30.471,3.86 32.159,2.172 37.071,2.172 v1(37.084,2.159)
  Bottom Layer 4 w0.178: U3.1@40.386,1.27 U3.1@40.538,1.27
  Bottom Layer 4 w0.254: R8.2@36.297,3.839 36.297,2.87 v1@37.033,2.134 ; v1(37.084,2.159) 37.973,1.27 U3.1@39.561,1.27 U3.1@40.386,1.27
EEDI: U1.17 U3.4 | length 19.1
  Top Layer 1 w0.178: U1.17@30.871,7.743 30.871,3.927 32.295,2.503 33.872,2.503 35.065,3.696 41.313,3.696 41.656,4.039 41.656,4.191 ; v1(41.123,5.029) 41.643,4.508 41.643,4.191
  Bottom Layer 4 w0.178: U3.4@39.091,5.08 U3.4@39.561,5.08 41.072,5.08 v1(41.123,5.029)
EEDO: U1.18 U3.3 | length 16.9
  Top Layer 1 w0.178: U1.18@31.271,7.743 31.271,4.035 32.466,2.84 33.701,2.84 34.887,4.026 39.967,4.026 40.132,4.191 v1@41.148,4.191 ; v1@41.11,4.229 v1(41.123,4.242)
  Bottom Layer 4 w0.178: U3.3@39.091,3.81 U3.3@39.561,3.81 40.818,3.81 v1@41.199,4.191
GND: C1.1 C2.1 C3.1 C4.1 C5.1 C6.1 C7.1 C8.1 C9.1 C10.1 C11.1 C12.1 C13.1 C14.1 C15.1 C16.1 C17.1 C18.1 C19.1 C20.1 C21.1 C22.1 C23.1 C26.1 C27.1 C28.1 C29.1 C30.1 C31.1 C32.1 C33.1 C34.1 J2.4 J2.7 R1.2 R3.1 R4.1 R6.2 R8.1 R9.1 R11.1 R15.1 U1.49 U2.8 U2.9 U2.EP U3.5 Y1.2 Y1.4 | length 53.9
  Top Layer 1 w0.254: v1(24.79,12.954) 24.841,12.903 C1.1@25.4,12.903 ; v1(24.816,9.322) C2.1@25.505,9.322 ; v1(24.816,10.795) 25.469,10.795 ccw(c25.469,10.882) C3.1@25.53,10.82 25.53,10.944 v1(25.171,11.303) ; v1(24.968,13.64) v1@24.994,13.64 ; v1@25.07,13.716 v1@24.994,13.64 ; C1.1@25.481,12.822 ccw(c25.53,12.871) C1.1@25.53,12.802 ; C1.1@25.481,12.822 C1.1@25.4,12.903 ; v1@25.552,6.604 v1(25.679,6.604) 25.679,7.017 25.632,7.065 C4.1@25.632,7.29 ; v1@33.147,17.78 33.147,17.446 C14.1@33.426,17.167 34.42,17.167 C15.1@34.442,17.145 ; v1(34.112,17.907) 34.442,17.577 C15.1@34.442,17.167 ; v1@24.994,13.64 25.019,13.64 25.429,13.23 C1.1@25.429,12.903 C1.1@25.4,12.903
  Top Layer 1 w0.305: C18.1@37.639,10.897 37.871,10.897 v1@38.176,11.201 ; R6.2@46.304,4.941 46.951,4.941 47.079,4.813 ; v1(47.396,5.131) 47.079,4.813 ; C23.1@47.473,4.42 47.079,4.813 ; v1(48.311,11.049) J2.7@49.62,11.049 ; v1(48.39,8.049) J2.4@49.62,8.049
  Top Layer 1 w0.381: v1(26.187,1.143) C7.1@27.317,1.143 ; v1(26.289,16.129) R1.2@27.029,16.129 ; v1(26.289,17.145) C6.1@27.029,17.145 27.029,17.929 v1(27.051,17.907) ; C5.1@27.029,15.113 R1.2@27.029,16.129 ; C6.1@27.029,17.123 R1.2@27.029,16.129 ; v1(27.33,2.032) 27.342,2.02 C7.1@27.342,1.143 ; C8.1@27.711,20.689 28.461,20.689 v1(28.473,20.701) ; C8.1@27.711,20.828 v1(27.711,21.59) ; C9.1@29.351,20.712 C9.1@29.362,20.701 ; C9.1@29.362,20.723 v1(29.362,21.463) ; C10.1@29.489,17.548 v1(29.489,18.288) ; C10.1@29.616,17.526 29.638,17.548 C11.1@30.505,17.548 ; v1(30.124,20.955) 30.15,20.98 Y1.4@31.509,20.98 Y1.4@31.623,20.98 ; v1(30.251,18.288) 30.505,18.034 C11.1@30.505,17.548 ; v1(31.14,17.78) 31.001,17.64 30.598,17.64 C11.1@30.505,17.548 ; v1(32.918,1.524) 32.664,1.524 32.282,1.141 32.523,0.9 32.512,0.889 v1(33.083,0.889) ; v1(32.974,5.562) 32.966,5.562 C13.1@33.448,5.08 33.448,4.34 v1(33.426,4.318) ; Y1.2@33.718,19.279 33.718,18.301 v1(34.112,17.907) ; v1(34.823,19.812) 34.845,19.79 C16.1@35.585,19.79 36.198,19.79 v1@36.22,19.812 ; v1(35.331,6.731) 35.458,6.731 35.861,6.328 C17.1@35.966,6.328 35.966,5.969 v1(36.22,5.715) ; v1(37.287,19.939) R3.1@38.188,19.939 ; R3.1@38.176,20.144 v1(38.176,20.955) ; C22.1@41.583,1.27 41.583,2.01 v1(41.605,2.032) ; R4.1@41.583,2.921 41.583,3.153 v1(41.986,3.556)
  Bottom Layer 4 w0.381: v1(14.605,15.303) 14.634,15.332 C34.1@14.634,16.129 14.634,16.259 15.265,16.891 v1(14.605,16.891) ; C33.1@14.634,5.944 C33.1@14.634,5.966 ; v1(14.668,9.08) 14.634,9.046 C33.1@14.634,5.966 ; v1(15.392,5.207) C33.1@14.634,5.966 ; v1(16.154,4.318) C31.1@16.92,4.318 16.916,4.315 17.018,4.213 v1(17.018,3.619) ; v1(16.256,17.59) 16.904,17.59 C32.1@16.942,17.628 ; v1(17.297,20.066) C30.1@18.885,20.066 v1(20.726,20.066) ; C29.1@28.092,7.515 28.092,8.255 ; v1(36.068,17.78) 36.195,17.653 R9.1@36.195,16.913 ; v1(36.22,5.715) 36.297,5.639 R8.1@36.297,4.899 ; v1(42.748,4.699) 43.129,5.08 U3.5@44.411,5.08 v1(44.577,5.08) U3.5@44.882,5.08
  other v1: 37.274,0.889 48.133,1.079 14.668,1.143 17.297,1.143 20.447,1.143 24.028,1.143 36.474,1.143 46.037,1.143 50.355,1.206 53.594,1.206 49.149,2.286 28.194,2.413 30.607,2.984 53.784,3.429 51.752,3.556 28.384,4.127 25.019,4.318 37.973,4.572 28.384,5.334 48.958,5.397 22.288,5.588 20.701,5.905 23.749,6.096 52.26,6.54 44.64,6.604 47.561,6.604 42.989,6.731 41.148,6.985 16.319,7.048 14.414,7.175 46.291,7.175 38.1,7.239 51.435,7.429 34.48,7.493 22.352,7.62 38.798,7.683 36.893,7.747 40.386,7.747 20.574,8.001 24.32,8.572 47.053,8.954 16.383,9.017 46.037,9.017 47.815,9.271 22.606,9.525 20.891,9.588 43.942,9.652 43.18,9.716 51.244,9.716 45.275,9.779 46.609,9.779 52.324,10.16 15.875,10.414 41.084,10.668 42.1,10.922 18.415,10.986 14.605,11.112 22.225,11.112 38.227,11.176 39.116,11.176 51.244,11.176 23.368,11.367 52.324,11.938 38.481,12.128 45.212,12.255 22.987,12.319 47.498,12.573 51.054,12.573 39.179,12.763 43.751,12.89 46.355,12.89 21.082,13.144 14.605,13.335 27.749,13.97 24.193,14.034 18.859,14.16 22.733,14.224 52.324,14.414 42.418,14.986 21.082,15.176 24.257,15.176 18.351,15.367 16.129,15.494 51.181,15.494 52.197,15.494 37.465,15.557 47.18,15.621 23.177,16.002 41.783,16.002 49.403,16.192 39.052,16.256 18.669,16.383 41.91,16.891 24.193,16.954 48.133,16.954 21.336,17.399 47.015,17.399 49.276,17.462 23.177,17.78 40.386,17.78 33.122,17.882 53.848,18.161 26.225,18.224 20.891,18.351 50.736,18.542 24.193,18.605 52.578,18.605 48.514,18.732 47.18,18.796 39.319,18.923 25.844,19.177 23.368,19.241 18.986,19.431 36.347,19.812 50.99,19.939 48.641,20.066 21.615,20.828 25.552,20.828 36.728,21.082 39.903,21.082 50.165,21.145 53.848,21.145 43.624,21.209 47.269,21.209
  other v2: 29.671,8.893 30.571,8.893 31.471,8.893 32.371,8.893 33.271,8.893 29.671,9.793 30.571,9.793 31.471,9.793 32.371,9.793 33.271,9.793 29.671,10.693 30.571,10.693 32.371,10.693 33.271,10.693 29.671,11.593 30.571,11.593 31.471,11.593 32.371,11.593 33.271,11.593 29.671,12.493 30.571,12.493 31.471,12.493 32.371,12.493 33.271,12.493 40.899,15.525 40.899,16.225
LED2: J1.13 U1.24 | length 35.3
  Top Layer 1 w0.178: v1(33.083,3.691) 33.536,3.691 34.709,4.864 34.709,6.439 33.671,7.477 U1.24@33.671,7.743
  Bottom Layer 4 w0.178: J1.13@4.216,3.683 J1.13@4.37,3.529 ; J1.13@4.318,3.529 J1.13@4.37,3.529 ; v1(33.083,3.691) 29.155,3.691 28.448,2.984 12.763,2.984 11.786,3.962 8.992,3.962 8.558,3.529 J1.13@4.37,3.529
LED3: J1.15 U1.33 | length 42.9
  Top Layer 1 w0.178: U1.33@34.421,11.693 35.214,11.693 36.97,13.449 36.97,15.354 36.589,15.735 36.589,18.021 35.687,18.923 v1(34.95,18.923)
  Bottom Layer 4 w0.178: J1.15@4.343,18.415 J1.15@4.343,18.542 ; J1.15@4.47,18.542 7.431,21.503 25.805,21.503 27.127,20.18 30.556,20.18 31.813,18.923 v1(34.95,18.923)
NetC5_2: C5.2 U1.48 | length 2.3
  Top Layer 1 w0.178: 29.083,14.084 29.096,14.084 ; U1.48@29.223,13.983 29.271,13.935 U1.48@29.271,13.643
  Top Layer 1 w0.203: 29.096,14.084 U1.48@29.21,13.97
  Top Layer 1 w0.229: 28.575,14.097 29.083,14.097
  Top Layer 1 w0.305: C5.2@28.089,15.113 28.089,14.583 28.575,14.097
NetC17_2: C17.2 FB1.1 U1.25
NetC20_2: C20.2 R5.1 U2.3 | length 12
  Bottom Layer 4 w0.203: U2.3@40.45,14.725 40.45,14.275 40.176,14.002 40.176,11.589 40.468,11.297 41.244,11.297 41.592,11.646 41.592,12.446 41.904,12.758 42.819,12.758 43.18,13.119 43.18,15.853 C20.2@43.583,16.256 R5.1@43.583,17.335
NetC31_2: C31.2 J1.7 | length 2.2
  Bottom Layer 4 w0.305: C31.2@17.98,4.318 19.167,4.318 19.736,4.887 J1.7@19.736,5.08
NetC32_2: C32.2 J1.12 | length 2.1
  Bottom Layer 4 w0.305: C32.2@17.98,17.653 18.494,17.139 19.488,17.139 J1.12@19.736,16.891
NetC33_2: C33.2 J1.1 | length 1.4
  Bottom Layer 4 w0.305: C33.2@15.694,5.944 17.043,5.944 J1.1@17.069,5.969
NetC34_2: C34.2 J1.6 | length 1.6
  Bottom Layer 4 w0.254: C34.2@15.694,16.129 J1.6@17.268,16.129
NetD1_2: D1.2 R3.2 | length 1.6
  Top Layer 1 w0.305: R3.2@39.546,19.939 R3.2@39.688,19.939 40.97,19.939 D1.2@41.123,19.787
NetJ1_14: J1.14 R13.1 | length 2.3
  Bottom Layer 4 w0.254: J1.14@1.714,3.544 J1.14@1.829,3.429
  Bottom Layer 4 w0.381: J1.14@1.803,3.429 2.45,2.782 R13.1@2.45,1.524
NetJ1_16: J1.16 R14.1 | length 1.9
  Bottom Layer 4 w0.381: J1.16@1.854,18.466 1.778,18.39 1.778,17.157 R14.1@2.146,16.789
NetR1_1: R1.1 U1.47 | length 3.2
  Top Layer 1 w0.178: R1.1@28.067,16.129 28.58,15.616 28.58,15.108 29.197,14.491 29.246,14.491 29.637,14.1 29.637,14.051 29.671,14.017 U1.47@29.671,13.643
NetR2_1: R2.1 U1.35 | length 4.9
  Top Layer 1 w0.178: U1.35@34.421,12.493 34.998,12.493 36.093,13.589 36.093,14.453 v1(35.433,15.113) 35.433,15.748 R2.1@35.687,16.002
NetR4_2: R4.2 U3.6 | length 3.1
  Top Layer 1 w0.178: R4.2@42.621,2.794 42.621,3.556 v1(42.875,3.81)
  Bottom Layer 4 w0.178: v1(42.875,3.81) U3.6@44.882,3.81
NetR7_1: R7.1 R15.2 U2.2 | length 2.6
  Bottom Layer 4 w0.178: U2.2@40.85,14.725 40.85,13.481 R7.1@40.83,13.462 40.83,12.217 R15.2@40.856,12.192
NetR10_1: R10.1 U1.23 | length 4.1
  Top Layer 1 w0.178: U1.23@33.274,7.747 33.274,7.239 33.782,6.731 v1(33.782,6.477)
  Bottom Layer 4 w0.178: v1(33.782,6.477) 34.442,6.477 35.281,5.639 R10.1@35.281,4.899
NetTP2_1: TP2.1 U2.4 U2.5 | length 1.2
  Bottom Layer 4 w0.178: TP2.1@39.624,13.525 39.65,13.551 U2.5@39.65,14.725
PME_MODE: TP1.1 U1.43 | length 12
  Top Layer 1 w0.178: TP1.1@26.365,20.523 26.365,19.964 v1@26.492,19.837 ; 31.128,14.961 v1@31.128,16.129 ; 31.14,14.961 31.271,14.83 U1.43@31.271,13.643
  Bottom Layer 4 w0.178: v1(26.289,19.812) 26.61,19.812 26.623,19.825 30.34,19.825 31.661,18.504 31.661,16.37 v1@31.242,15.951 ; v1@31.242,16.002 v1(31.267,16.002)
PME_N/CONNECT: R12.1 U1.22 | length 3.8
  Top Layer 1 w0.178: U1.22@32.871,7.743 32.871,7.109 33.172,6.807 33.172,6.325 v1@33.782,5.715 ; v1@33.744,5.677 33.782,5.639 33.807,5.664 v1(33.807,5.791) 33.758,5.791 v1@33.807,5.842
  Bottom Layer 4 w0.178: v1(33.807,5.791) 33.807,5.766 33.782,5.74 34.112,5.41 R12.1@34.112,4.899
RJ45_CHASSIS: C30.2 J1.0 | length 3.4
  Bottom Layer 4 w1.27: J1.0@10.592,6.148 J1.0@10.668,6.224 ; J1.0@10.973,19.812 11.227,20.066 C30.2@14.135,20.066
  other v1: 5.016,0.889 7.747,0.889 12.002,0.889 0.889,2.286 13.462,4.318 0.889,4.763 0.889,7.239 13.271,7.366 0.889,9.906 13.271,10.287 0.889,12.827 13.271,13.399 0.953,15.557 13.271,17.081 1.333,20.955 8.7,20.955 3.873,21.209 6.286,21.209
TEST: R9.2 U1.34 | length 5.1
  Top Layer 1 w0.178: U1.34@34.421,12.093 35.106,12.093 36.474,13.462 36.474,14.834 v1(36.195,15.113)
  Bottom Layer 4 w0.229: v1(36.195,15.113) R9.2@36.195,15.853
TR0_N: J1.10 U1.2 | length 19.8
  Top Layer 1 w0.178: J1.10@19.808,13.079 20.699,13.97 21.488,13.97 22.631,15.113 22.631,19.66 22.936,19.964 24.613,19.964 24.917,19.66 24.917,15.463 27.757,12.624 27.762,12.624 27.893,12.493 U1.2@28.521,12.493
TR0_P: J1.11 U1.1 | length 19.7
  Top Layer 1 w0.178: J1.11@19.808,15.109 20.566,14.351 21.331,14.351 22.25,15.271 22.25,19.817 22.778,20.345 24.77,20.345 25.298,19.817 25.298,15.621 27.838,13.081 27.844,13.081 28.032,12.893 U1.1@28.521,12.893
TR1_N: J1.5 U1.5 | length 19.1
  Top Layer 1 w0.178: v1(16.281,12.7) 16.027,12.7 15.646,12.319 15.646,11.43 15.99,11.086 17.715,11.086 18.313,11.684 21.742,11.684 22.25,12.192 22.25,12.802 22.479,13.03 23.673,13.03 23.876,12.827 23.876,12.263 24.277,11.862 26.365,11.862 ; J1.5@17.221,13.64 J1.5@17.221,14.046 ; 26.362,11.859 26.919,11.303 28.022,11.303 28.032,11.293 U1.5@28.521,11.293
  Bottom Layer 4 w0.178: v1(16.281,12.7) 16.459,12.7 17.221,13.462 J1.5@17.221,13.97
TR1_P: J1.4 U1.4 | length 19.7
  Top Layer 1 w0.178: J1.4@17.297,11.938 17.297,12.035 J1.4@17.268,12.064 17.268,12.486 16.29,13.464 16.29,14.499 16.863,15.072 17.673,15.072 18.246,14.499 18.246,12.641 18.821,12.065 21.585,12.065 21.869,12.35 21.869,12.959 22.321,13.411 22.555,13.411 22.626,13.411 23.831,13.411 24.257,12.985 24.257,12.421 24.435,12.243 26.523,12.243 26.746,12.02 26.746,12.014 27.077,11.684 28.022,11.684 28.032,11.693 U1.4@28.521,11.693
TR2_N: J1.2 U1.8 | length 19.6
  Top Layer 1 w0.178: J1.2@17.268,8.004 17.268,8.5 cw(c17.404,8.5) 17.308,8.596 17.475,8.763 18.217,8.763 18.821,9.367 18.821,10.033 19.075,10.287 21.28,10.287 21.615,9.951 21.615,8.763 21.184,8.331 21.184,7.081 21.788,6.477 23.012,6.477 23.647,7.112 23.647,9.367 24.186,9.906 27.261,9.906 27.457,10.103 28.022,10.103 28.032,10.093 U1.8@28.521,10.093
TR2_P: J1.3 U1.7 | length 20.2
  Top Layer 1 w0.178: J1.3@17.268,10.034 17.268,9.427 J1.3@17.297,9.398 ; J1.3@17.283,10.019 J1.3@17.297,9.398 ; U1.7@28.521,10.493 28.032,10.493 28.022,10.484 27.3,10.484 27.09,10.274 24.016,10.274 23.266,9.525 23.266,7.27 22.855,6.858 21.946,6.858 21.565,7.239 21.565,8.173 21.996,8.605 21.996,10.109 21.438,10.668 18.918,10.668 18.44,10.191 18.44,9.525 18.186,9.271 17.424,9.271 J1.3@17.297,9.398
TR3_N: J1.9 U1.11 | length 19.7
  Top Layer 1 w0.178: J1.9@19.808,9.019 19.808,8.226 19.71,8.128 18.791,8.128 18.313,7.651 18.313,4.445 19.202,3.556 22.916,3.556 25.044,5.684 25.044,7.747 25.298,8.001 27.139,8.001 28.032,8.893 U1.11@28.521,8.893
TR3_P: J1.8 U1.10 | length 19.7
  Top Layer 1 w0.178: J1.8@19.808,6.989 19.808,7.522 19.583,7.747 18.948,7.747 18.694,7.493 18.694,4.603 19.36,3.937 21.107,3.937 21.234,4.064 21.234,4.648 21.438,4.851 22.047,4.851 22.25,4.648 22.25,4.039 22.352,3.937 22.758,3.937 24.663,5.842 24.663,7.905 25.141,8.382 26.981,8.382 27.893,9.293 U1.10@28.521,9.293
